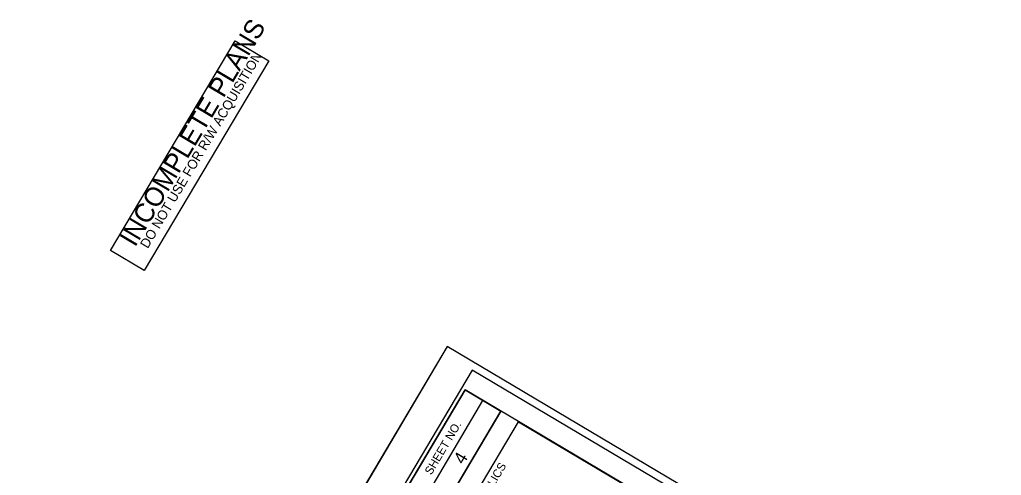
# Model space of a CAD drawing. Extents: x 2137081 to 2142019, y 404041 to 411238.
# Drawn here: x 2140819 to 2141411, y 410964 to 411238 of the extents above; entities that cross this region are included whole.
import ezdxf

# ---------------------------------------------------------------- set-up
doc = ezdxf.new("R2010")
doc.units = 0
for name, color, linetype in [('Sheet Cutting Line CELL', 7, 'Continuous'), ('Sheet Data Field CELL', 7, 'Continuous'), ('Sheet Plan And Profile CELL', 7, 'Continuous'), ('Sheet Plot Border Inside CELL', 7, 'Continuous'), ('Sheet Plot Border Outside CELL', 7, 'Continuous'), ('Sheet Sticker Incomplete CELL', 7, 'Continuous')]:
    doc.layers.add(name, color=color, linetype=linetype)

msp = doc.modelspace()

# ---------------------------------------------------------------- linework, layer by layer
at = {"layer": 'Sheet Cutting Line CELL'}
msp.add_line((2141076.97, 411041.05), (2140217.7, 409593.35), dxfattribs=at)
at = {"layer": 'Sheet Plan And Profile CELL'}
for p, q in [((2140996.33, 410836.51), (2141098.43, 411008.54)), ((2141007.08, 410830.13), (2141109.18, 411002.16))]:
    msp.add_line(p, q, dxfattribs=at)
for points in [[(2141087.64, 411014.95), (2140322.04, 409725.04), (2141224.97, 409189.12), (2141990.57, 410479.02)], [(2140985.54, 410842.92), (2141087.64, 411014.95), (2141109.18, 411002.16), (2141007.08, 410830.13)], [(2141068.89, 410909.79), (2141119.93, 410995.78), (2141216.67, 410938.36), (2141165.63, 410852.37)]]:
    msp.add_lwpolyline(points, close=True, dxfattribs=at)
at = {"layer": 'Sheet Plot Border Inside CELL'}
msp.add_lwpolyline([(2141148.77, 409055.84), (2141999.1, 410488.49), (2141091.87, 411026.97), (2140241.54, 409594.32)], close=True, dxfattribs=at)
at = {"layer": 'Sheet Plot Border Outside CELL'}
msp.add_lwpolyline([(2141159.33, 409034.46), (2142018.6, 410482.16), (2141076.97, 411041.05), (2140217.7, 409593.35)], close=True, dxfattribs=at)
at = {"layer": 'Sheet Sticker Incomplete CELL'}
msp.add_lwpolyline([(2140894.31, 411086.86), (2140874.1, 411098.86), (2140949.13, 411225.27), (2140969.33, 411213.27)], close=True, dxfattribs=at)

# ---------------------------------------------------------------- texts
at = {"layer": 'Sheet Data Field CELL'}
msp.add_text('4', height=7.75, rotation=59.30926, dxfattribs=at).set_placement((2141086.77, 410969.59))
at = {"layer": 'Sheet Plan And Profile CELL'}
for s, p in [('SHEET NO.', (2141067.29, 410963.42)), ('HYDRAULICS', (2141090.71, 410932.25))]:
    msp.add_text(s, height=5, rotation=59.30926, dxfattribs=at).set_placement(p)
at = {"layer": 'Sheet Sticker Incomplete CELL'}
for s, height, p in [('INCOMPLETE PLANS', 11.52, (2140888.81, 411100.53)), ('DO NOT USE FOR R/W ACQUISITION', 5.76, (2140896.45, 411099.78))]:
    msp.add_text(s, height=height, rotation=59.30926, dxfattribs=at).set_placement(p)

doc.saveas('drawing.dxf')
